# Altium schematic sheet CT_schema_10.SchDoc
size 254 x 194 mm
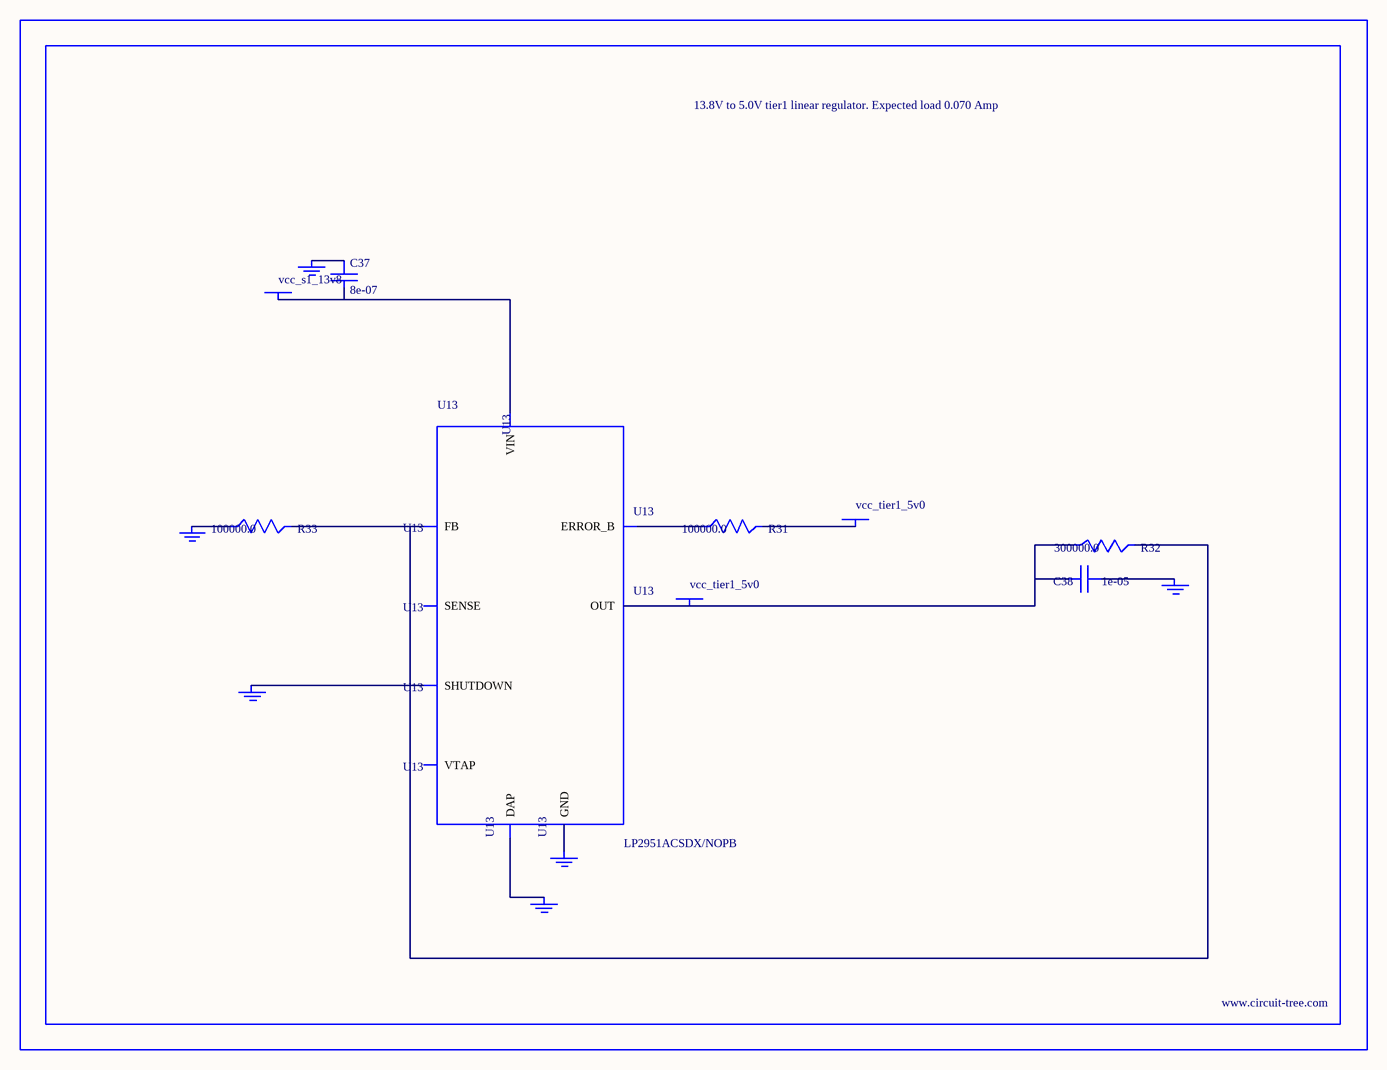
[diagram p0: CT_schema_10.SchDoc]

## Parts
BORDER9  (no value)
C37  8e-07  [R0603]
C38  1e-05  [C1210]
GND_INSTANCE_9_0  (no value)
GND_INSTANCE_9_1  (no value)
GND_INSTANCE_9_2  (no value)
GND_INSTANCE_9_3  (no value)
GND_INSTANCE_9_4  (no value)
GND_INSTANCE_9_5  (no value)
POWER_INSTANCE_9_0  vcc_tier1_5v0
POWER_INSTANCE_9_1  vcc_s1_13v8
POWER_INSTANCE_9_2  vcc_tier1_5v0
R31  100000.0  [R0603]
R32  300000.0  [R0603]
R33  100000.0  [R0603]
U13  LP2951ACSDX/NOPB  [WSON-8]

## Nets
NetC37_1: C37.1 GND_INSTANCE_9_3.0(GND)
NetC37_2: C37.2 POWER_INSTANCE_9_1.0(PWR) U13.8(VIN)
NetC38_1: C38.1 GND_INSTANCE_9_0.0(GND)
NetC38_2: C38.2 POWER_INSTANCE_9_2.0(PWR) R32.1 U13.1(OUT)
NetGND_INSTANCE_9_1_0: GND_INSTANCE_9_1.0(GND) U13.3(SHUTDOWN)
NetGND_INSTANCE_9_2_0: GND_INSTANCE_9_2.0(GND) R33.1
NetGND_INSTANCE_9_4_0: GND_INSTANCE_9_4.0(GND) U13.PAD(DAP)
NetGND_INSTANCE_9_5_0: GND_INSTANCE_9_5.0(GND) U13.4(GND)
NetPOWER_INSTANCE_9_0_0: POWER_INSTANCE_9_0.0(PWR) R31.2
NetR31_1: R31.1 U13.5(ERROR_B)
NetR32_2: R32.2 R33.2 U13.7(FB)

Not connected (* = marked no-connect by the designer): U13 2(SENSE) 6(VTAP)

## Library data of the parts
BORDER9 = BORDER_PAGE9
C37 = C37
C38 = GRM32DR61E106MA12L
GND_INSTANCE_9_0-GND_INSTANCE_9_5 = GND
POWER_INSTANCE_9_0-POWER_INSTANCE_9_2 = PWR
R31 R33 = RC0603JR-07100KL
R32 = RC0603JR-07300KL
